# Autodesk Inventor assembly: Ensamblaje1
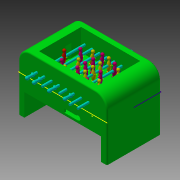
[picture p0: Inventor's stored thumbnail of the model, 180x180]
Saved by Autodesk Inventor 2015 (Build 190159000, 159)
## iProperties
Created: 2016-05
Part Number: Ensamblaje1
Document SubType Name: Assembly
Designer: ALEX
Author: ALEX
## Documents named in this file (4)
- C:\Users\ALEX\Desktop\innovacion\Ensamblaje1.iam
- C:\Users\ALEX\Desktop\innovacion\mesa.ipt
- C:\Users\ALEX\Desktop\innovacion\muñeco.ipt
- C:\Users\ALEX\Desktop\innovacion\mango.ipt
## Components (31 placed, 3 different names)
1. mesa:1 — Coincidencia:1, Coincidencia:3, Coincidencia:4, Coincidencia:5, Coincidencia:6, Coincidencia:7, Coincidencia:8, Coincidencia:9
2. muñeco:2 — Coincidencia:2
3. mango:1 — Coincidencia:1, Coincidencia:2
4. mango:2 — Coincidencia:5, Coincidencia:15, Coincidencia:16, Coincidencia:17, Coincidencia:18, Coincidencia:19
5. mango:3 — Coincidencia:7, Coincidencia:25, Coincidencia:26, Coincidencia:27
6. mango:4 — Coincidencia:8, Coincidencia:28, Coincidencia:29
7. mango:5 — Coincidencia:6, Coincidencia:20, Coincidencia:21, Coincidencia:22, Coincidencia:23, Coincidencia:24
8. mango:6 — Coincidencia:9, Coincidencia:30
9. mango:7 — Coincidencia:4, Coincidencia:12, Coincidencia:13, Coincidencia:14
10. mango:8 — Coincidencia:3, Coincidencia:10, Coincidencia:11
11. muñeco:3 — Coincidencia:16
12. muñeco:4 — Coincidencia:12
13. muñeco:5 — Coincidencia:11
14. muñeco:6 — Coincidencia:10
15. muñeco:7 — Coincidencia:14
16. muñeco:8 — Coincidencia:13
17. muñeco:9 — Coincidencia:17
18. muñeco:10 — Coincidencia:15
19. muñeco:11 — Coincidencia:18
20. muñeco:12 — Coincidencia:20
21. muñeco:13 — Coincidencia:19
22. muñeco:15 — Coincidencia:30
23. muñeco:16 — Coincidencia:29
24. muñeco:17 — Coincidencia:28
25. muñeco:18 — Coincidencia:27
26. muñeco:19 — Coincidencia:25
27. muñeco:20 — Coincidencia:26
28. muñeco:21 — Coincidencia:23
29. muñeco:22 — Coincidencia:21
30. muñeco:23 — Coincidencia:24
31. muñeco:24 — Coincidencia:22
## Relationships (30: Mate 30)
- Coincidencia:1 [Mate]: mesa:1 ↔ mango:1
- Coincidencia:2 [Mate]: muñeco:2 ↔ mango:1
- Coincidencia:3 [Mate]: mesa:1 ↔ mango:8
- Coincidencia:4 [Mate]: mesa:1 ↔ mango:7
- Coincidencia:5 [Mate]: mesa:1 ↔ mango:2
- Coincidencia:6 [Mate]: mesa:1 ↔ mango:5
- Coincidencia:7 [Mate]: mesa:1 ↔ mango:3
- Coincidencia:8 [Mate]: mesa:1 ↔ mango:4
- Coincidencia:9 [Mate]: mesa:1 ↔ mango:6
- Coincidencia:10 [Mate]: mango:8 ↔ muñeco:6
- Coincidencia:11 [Mate]: mango:8 ↔ muñeco:5
- Coincidencia:12 [Mate]: mango:7 ↔ muñeco:4
- Coincidencia:13 [Mate]: mango:7 ↔ muñeco:8
- Coincidencia:14 [Mate]: mango:7 ↔ muñeco:7
- Coincidencia:15 [Mate]: mango:2 ↔ muñeco:10
- Coincidencia:16 [Mate]: mango:2 ↔ muñeco:3
- Coincidencia:17 [Mate]: mango:2 ↔ muñeco:9
- Coincidencia:18 [Mate]: mango:2 ↔ muñeco:11
- Coincidencia:19 [Mate]: mango:2 ↔ muñeco:13
- Coincidencia:20 [Mate]: mango:5 ↔ muñeco:12
- Coincidencia:21 [Mate]: mango:5 ↔ muñeco:22
- Coincidencia:22 [Mate]: mango:5 ↔ muñeco:24
- Coincidencia:23 [Mate]: mango:5 ↔ muñeco:21
- Coincidencia:24 [Mate]: mango:5 ↔ muñeco:23
- Coincidencia:25 [Mate]: mango:3 ↔ muñeco:19
- Coincidencia:26 [Mate]: mango:3 ↔ muñeco:20
- Coincidencia:27 [Mate]: mango:3 ↔ muñeco:18
- Coincidencia:28 [Mate]: mango:4 ↔ muñeco:17
- Coincidencia:29 [Mate]: mango:4 ↔ muñeco:16
- Coincidencia:30 [Mate]: mango:6 ↔ muñeco:15
